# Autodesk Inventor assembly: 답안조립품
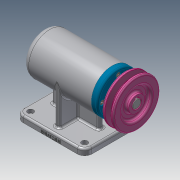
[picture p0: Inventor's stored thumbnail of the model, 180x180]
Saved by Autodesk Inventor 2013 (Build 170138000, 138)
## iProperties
Created: 2020-10
Part Number: 답안조립품
Document SubType Name: Assembly
Designer: user
Author: user
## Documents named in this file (12)
- C:\Users\user\Desktop\701004v1026\답안조립품.iam
- C:\Users\user\Desktop\701004v1026\본체.ipt
- C:\Users\user\Desktop\701004v1026\V벨트풀리.ipt
- C:\Users\user\Desktop\701004v1026\멈춤나사 M3.ipt
- C:\Users\user\Desktop\701004v1026\베어링 6004.ipt
- C:\Users\user\Desktop\701004v1026\베어링 51202.ipt
- C:\Users\user\Desktop\701004v1026\볼트 M4.ipt
- C:\Users\user\Desktop\701004v1026\어댑터슬리브.ipt
- C:\Users\user\Desktop\701004v1026\오일 실.ipt
- C:\Users\user\Desktop\701004v1026\축.ipt
- C:\Users\user\Desktop\701004v1026\커버.ipt
- C:\Users\user\Desktop\701004v1026\키 5 x 5 x 16.ipt
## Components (1 placed, 1 different names)
1. V벨트풀리:1 — 플러쉬:1
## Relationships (1: Flush 1)
- 플러쉬:1 [Flush]: V벨트풀리:1
